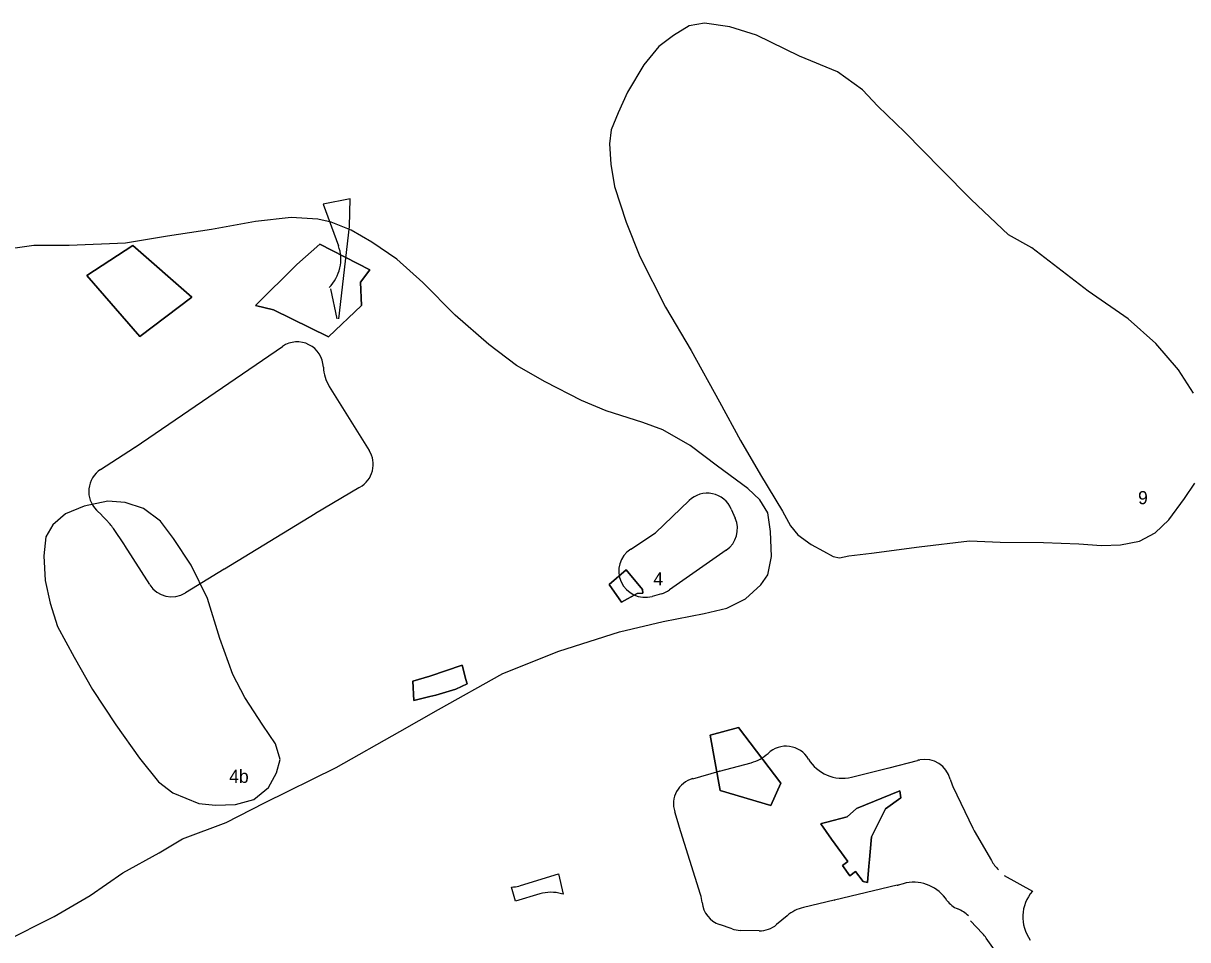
# Model space of a CAD drawing. Extents: x -445049 to -430649, y -1142304 to -1129816.
# Drawn here: x -443912 to -443023, y -1133134 to -1132434 of the extents above; entities that cross this region are included whole.
import ezdxf

# ---------------------------------------------------------------- set-up
doc = ezdxf.new("R2010")
doc.units = 0
for name, color, linetype in [('Vrstva 23', 7, 'Continuous'), ('Vrstva 51', 7, 'Continuous'), ('Vrstva 7', 7, 'Continuous')]:
    doc.layers.add(name, color=color, linetype=linetype)

msp = doc.modelspace()

# ---------------------------------------------------------------- linework, layer by layer
at = {"layer": 'Vrstva 23'}
for p, q in [((-443677.2, -1132636.66), (-443672.36, -1132659.53)), ((-443826.33, -1132757.45), (-443713.91, -1132680.67)), ((-443678.1, -1132711.26), (-443647.59, -1132760.03)), ((-443852.69, -1132774.68), (-443826.84, -1132757.8)), ((-443655.53, -1132788.52), (-443688.59, -1132808.22)), ((-443851.84, -1132809.61), (-443855.88, -1132805.59)), ((-443688.86, -1132808.38), (-443758.18, -1132850.65)), ((-443371.2, -1132804.79), (-443368.17, -1132811.8)), ((-443845.46, -1132816.41), (-443848.81, -1132812.68)), ((-443834.59, -1132832.03), (-443842.94, -1132819.65)), ((-443815.22, -1132862.54), (-443834.13, -1132832.74)), ((-443375.02, -1132836.12), (-443418.43, -1132866.6)), ((-443758.26, -1132850.7), (-443787.87, -1132868.88)), ((-443424.57, -1132869.5), (-443431.72, -1132871.48)), ((-443250.62, -1133002.33), (-443229.15, -1132996.77)), ((-443228.1, -1132996.53), (-443227.4, -1132996.39)), ((-443400.71, -1133010.65), (-443380.4, -1133005.02)), ((-443380.26, -1133004.98), (-443355.96, -1132998.44)), ((-443279.39, -1133009.4), (-443250.99, -1133002.43)), ((-443202.04, -1133016.63), (-443186.84, -1133048.43)), ((-443410.96, -1133046.98), (-443414.44, -1133035.94)), ((-443394.67, -1133099.04), (-443410.94, -1133047.05)), ((-443185.78, -1133050.44), (-443172.68, -1133073.24)), ((-443162.86, -1133084.64), (-443141.31, -1133096.58)), ((-443244.47, -1133092.05), (-443292.56, -1133103.48)), ((-443239.99, -1133090.82), (-443243.74, -1133091.86)), ((-443499.6, -1133098.8), (-443500.76, -1133098.48)), ((-443292.65, -1133103.51), (-443316.12, -1133108.96)), ((-443206.59, -1133103.57), (-443207.78, -1133101.95)), ((-443370.67, -1133125.37), (-443380.11, -1133122.07)), ((-443332.71, -1133118.66), (-443336.64, -1133122.01)), ((-443328.69, -1133115.27), (-443332.62, -1133118.58)), ((-443179.41, -1133128.87), (-443188.71, -1133119.22)), ((-443350.04, -1133126.78), (-443364.51, -1133126.48))]:
    msp.add_line(p, q, dxfattribs=at)
for points in [[(-443670.87, -1132659.7), (-443662.77, -1132589.04), (-443662.25, -1132567.97), (-443682.82, -1132572.18), (-443671.15, -1132603.81)], [(-443448.03, -1132835.48), (-443428.97, -1132822.99), (-443403.44, -1132798.36)], [(-443532.2, -1133092.22), (-443503.17, -1133083.21), (-443499.6, -1133098.8)], [(-443517.4, -1133098.66), (-443535.96, -1133104.24), (-443538.96, -1133093.54), (-443537.4, -1133093.34)], [(-443103.8, -1133213.9), (-443113.59, -1133220.86), (-443176.56, -1133132.31)]]:
    msp.add_lwpolyline(points, dxfattribs=at)
for centre, radius, start, end in [((-443699.29, -1132614.2), 30, 314.42043, 20.25618), ((-443702.63, -1132697.18), 20, 2.10176, 124.3337), ((-443652.66, -1132695.35), 30, 182.10176, 212.02791), ((-443843.25, -1132732.68), 30, 303.15924, 304.33371), ((-443664.54, -1132770.64), 20, 299.16865, 32.02791), ((-443841.75, -1132791.43), 20, 123.15924, 225.0635), ((-443640.18, -1132814.3), 30, 119.16865, 120.78723), ((-443389.55, -1132812.75), 20, 23.43675, 133.9791), ((-443873.03, -1132830.85), 30, 44.03693, 45.0635), ((-443837.09, -1132796.1), 20, 224.03693, 227.0475), ((-443871.16, -1132832.69), 30, 41.84119, 47.0475), ((-443673.24, -1132834), 30, 120.78723, 121.37077), ((-443867.81, -1132836.43), 30, 33.99357, 41.84119), ((-443386.51, -1132819.75), 20, 305.071, 23.43675), ((-443859.46, -1132848.8), 30, 32.38493, 33.99357), ((-443437.07, -1132852.21), 20, 123.2296, 285.51431), ((-443742.57, -1132876.27), 30, 121.37077, 121.54625), ((-443798.34, -1132851.83), 20, 212.38493, 301.54625), ((-443429.92, -1132850.23), 20, 285.51431, 305.071), ((-443329.49, -1133005.88), 20, 30.81364, 133.26556), ((-443363.76, -1132969.47), 30, 285.07078, 313.26556), ((-443286.55, -1132980.27), 30, 210.81364, 283.80053), ((-443224.13, -1133016.13), 20, 101.44355, 104.52763), ((-443223.43, -1133015.99), 20, 14.23712, 101.44355), ((-443375.06, -1133024.3), 20, 105.07078, 105.47705), ((-443258.15, -1132973.29), 30, 283.80053, 284.52763), ((-443395.37, -1133029.92), 20, 105.47705, 197.51206), ((-443174.97, -1133003.69), 30, 194.23712, 205.54552), ((-443439.57, -1133056.01), 30, 17.38, 17.51206), ((-443159.77, -1133035.49), 30, 205.54552, 209.88212), ((-443146.67, -1133058.29), 30, 209.88212, 226.72454), ((-443541.09, -1133063.57), 30, 277.06067, 287.23966), ((-443249.1, -1133072.59), 20, 283.37402, 285.53896), ((-443231.95, -1133119.72), 30, 36.33833, 105.53896), ((-443508.76, -1133127.39), 30, 74.53249, 106.73425), ((-443423.3, -1133108), 30, 5.52393, 17.38), ((-443297.18, -1133084.03), 20, 283.08603, 283.37402), ((-443190.48, -1133091.72), 20, 216.33833, 246.75567), ((-443118.68, -1133116.27), 30, 138.97955, 215.86626), ((-443373.53, -1133103.19), 20, 185.52393, 250.77659), ((-443309.33, -1133138.18), 30, 103.08603, 130.19033), ((-443210.21, -1133137.66), 30, 48.01849, 66.75567), ((-443349.61, -1133106.79), 20, 268.784, 310.4326), ((-443313.26, -1133141.5), 30, 130.19033, 130.4326), ((-443364.08, -1133106.48), 20, 250.77659, 268.784), ((-443201.01, -1133149.69), 30, 35.41387, 43.94189)]:
    msp.add_arc(centre, radius, start, end, dxfattribs=at)
at = {"layer": 'Vrstva 51'}
for points in [[(-443018.34, -1132716.27), (-443029.71, -1132698.63), (-443047.02, -1132678.5), (-443068.13, -1132659.72), (-443098.88, -1132638.57), (-443125.18, -1132618.17), (-443141.83, -1132605.46), (-443159.51, -1132595.53), (-443188.17, -1132568.41), (-443211, -1132545.4), (-443238.76, -1132517.11), (-443259.36, -1132497.14), (-443271.13, -1132484.8), (-443290.15, -1132471.08), (-443319.14, -1132459.08), (-443351.91, -1132443.11), (-443372.31, -1132436.66), (-443391.75, -1132433.97), (-443403.37, -1132435.96), (-443415.38, -1132443.25), (-443426.66, -1132451.81), (-443437.94, -1132465.7), (-443450.56, -1132486.45), (-443457.48, -1132502.31), (-443462.97, -1132515.4), (-443464.17, -1132525.96), (-443463.3, -1132541.58), (-443460.48, -1132558.57), (-443451.48, -1132585.86), (-443441.17, -1132612.02), (-443421.56, -1132650.74), (-443401.94, -1132683.74), (-443380.33, -1132723.03), (-443364.12, -1132752.49), (-443348.89, -1132778.61), (-443332.16, -1132806.48), (-443326.03, -1132817.58), (-443320.42, -1132824.56), (-443310.32, -1132831.86), (-443300.89, -1132837.08), (-443293.4, -1132840.92), (-443288.58, -1132842.1), (-443281.5, -1132840.58), (-443264.16, -1132838.61), (-443227.76, -1132833.57), (-443189.35, -1132829.09), (-443166.08, -1132830.02), (-443132.96, -1132830.46), (-443106, -1132831.26), (-443088.5, -1132832.58), (-443074.13, -1132832.02), (-443059.6, -1132829.43), (-443047.65, -1132822.96), (-443037.09, -1132813.11), (-443025.22, -1132796.81), (-443017.38, -1132785.12)], [(-443926.51, -1133135.09), (-443888.12, -1133115.97), (-443860.74, -1133099.76), (-443835.78, -1133082.54), (-443808.05, -1133067.18), (-443790.22, -1133056.48), (-443756.9, -1133044.04), (-443727.55, -1133029.22), (-443672.79, -1133002.2), (-443624.21, -1132974.71), (-443594.71, -1132957.83), (-443545.73, -1132930.37), (-443502.92, -1132913.24), (-443456.55, -1132898.46), (-443423.15, -1132890.59), (-443391.98, -1132884.63), (-443374.65, -1132880.53), (-443360.4, -1132873.3), (-443348.79, -1132862.55), (-443343.25, -1132855.08), (-443340.54, -1132841.16), (-443341.18, -1132822.01), (-443343.43, -1132807.73), (-443349.32, -1132797.73), (-443358.64, -1132789.14), (-443381.85, -1132772.04), (-443402.68, -1132756.35), (-443423.37, -1132744.42), (-443438.72, -1132738.69), (-443466.71, -1132729.95), (-443485.62, -1132721.88), (-443513.21, -1132707.76), (-443535.11, -1132695.32), (-443556.32, -1132679.2), (-443582.05, -1132656.92), (-443606.74, -1132631.81), (-443626.58, -1132614.12), (-443645.53, -1132601.07), (-443661.46, -1132591.98), (-443676.77, -1132585.85), (-443686.97, -1132583.42), (-443707.23, -1132582.31), (-443734.44, -1132585.25), (-443768.13, -1132591.44), (-443801.72, -1132596.39), (-443833.69, -1132601.87), (-443876.58, -1132603.63), (-443903.58, -1132603.67), (-443930.85, -1132607.44)]]:
    msp.add_lwpolyline(points, dxfattribs=at)
msp.add_lwpolyline([(-443894.56, -1132826.08), (-443896.06, -1132840.5), (-443894.98, -1132859.26), (-443891.29, -1132876.57), (-443885.58, -1132894.43), (-443872.8, -1132917.82), (-443858.88, -1132942.53), (-443840.99, -1132969.62), (-443822.97, -1132995.06), (-443808.56, -1133013.16), (-443797.55, -1133021.47), (-443777.82, -1133029.59), (-443765.05, -1133030.97), (-443749.65, -1133030.47), (-443735.65, -1133026.54), (-443724.59, -1133017.4), (-443718.35, -1133006.25), (-443715.51, -1132996.08), (-443719.18, -1132984.18), (-443728.89, -1132969.74), (-443742.68, -1132948.78), (-443751.73, -1132931.07), (-443761.71, -1132903.75), (-443771.04, -1132873.15), (-443783.66, -1132847.7), (-443797.06, -1132827.18), (-443806.87, -1132813.99), (-443819.84, -1132804.29), (-443834.04, -1132799.9), (-443847.25, -1132798.91), (-443865.38, -1132802.53), (-443879.53, -1132808.52), (-443889.3, -1132816.92)], close=True, dxfattribs=at)
at = {"layer": 'Vrstva 7'}
for points in [[(-443828.15, -1132603.55), (-443863.1, -1132626.63), (-443822.73, -1132673.2), (-443783.07, -1132643.01)], [(-443647.09, -1132622.27), (-443685.3, -1132602.68), (-443702.95, -1132618), (-443734.43, -1132649.42), (-443720.76, -1132652.69), (-443678.64, -1132673.29), (-443653.44, -1132649.34), (-443654.17, -1132631.61)], [(-443451.46, -1132851.14), (-443464.57, -1132862.35), (-443456.8, -1132873.4), (-443455.08, -1132875.85), (-443443.13, -1132869.24), (-443438.81, -1132868.96), (-443439.05, -1132866.23)], [(-443614.24, -1132936.31), (-443613.52, -1132951.03), (-443601.24, -1132948), (-443596.87, -1132946.92), (-443581.63, -1132942.44), (-443572.9, -1132938.2), (-443573.78, -1132934.82), (-443576.57, -1132924.01), (-443601.31, -1132932.37)], [(-443365.67, -1132971.65), (-443387.46, -1132977.55), (-443379.8, -1133019.76), (-443341.01, -1133031.01), (-443333.3, -1133014.03)], [(-443242.5, -1133019.89), (-443275.64, -1133033.38), (-443282.8, -1133039.75), (-443298.4, -1133043.79), (-443302.31, -1133044.8), (-443302.95, -1133045.12), (-443294.61, -1133056.94), (-443282.3, -1133073.98), (-443286.39, -1133076.88), (-443280.78, -1133084.79), (-443276.33, -1133081.63), (-443270.55, -1133089.05), (-443267.19, -1133089.91), (-443266.16, -1133077.45), (-443265.74, -1133072.42), (-443265.24, -1133066.45), (-443264.3, -1133055.13), (-443262.99, -1133052.52), (-443253.53, -1133033.63), (-443241.79, -1133025.28)]]:
    msp.add_lwpolyline(points, close=True, dxfattribs=at)
for points in [[(-443828.15, -1132603.55), (-443783.07, -1132643.01), (-443822.73, -1132673.2), (-443863.1, -1132626.63), (-443828.15, -1132603.55)], [(-443863.1, -1132626.63), (-443828.15, -1132603.55), (-443783.07, -1132643.01), (-443822.73, -1132673.2), (-443863.1, -1132626.63)], [(-443828.15, -1132603.55), (-443783.07, -1132643.01), (-443822.73, -1132673.2), (-443863.1, -1132626.63), (-443828.15, -1132603.55)], [(-443822.73, -1132673.2), (-443863.1, -1132626.63), (-443828.15, -1132603.55), (-443783.07, -1132643.01), (-443822.73, -1132673.2)], [(-443647.09, -1132622.27), (-443654.17, -1132631.61), (-443653.44, -1132649.34), (-443678.64, -1132673.29), (-443720.76, -1132652.69), (-443734.43, -1132649.42), (-443702.95, -1132618), (-443685.3, -1132602.68), (-443647.09, -1132622.27)], [(-443685.3, -1132602.68), (-443647.09, -1132622.27), (-443654.17, -1132631.61), (-443653.44, -1132649.34), (-443678.64, -1132673.29), (-443720.76, -1132652.69), (-443734.43, -1132649.42), (-443702.95, -1132618), (-443685.3, -1132602.68)], [(-443734.43, -1132649.42), (-443702.95, -1132618), (-443685.3, -1132602.68), (-443647.09, -1132622.27), (-443654.17, -1132631.61), (-443653.44, -1132649.34), (-443678.64, -1132673.29), (-443720.76, -1132652.69), (-443734.43, -1132649.42)], [(-443720.76, -1132652.69), (-443734.43, -1132649.42), (-443702.95, -1132618), (-443685.3, -1132602.68), (-443647.09, -1132622.27), (-443654.17, -1132631.61), (-443653.44, -1132649.34), (-443678.64, -1132673.29), (-443720.76, -1132652.69)], [(-443451.46, -1132851.14), (-443439.05, -1132866.23), (-443438.81, -1132868.96), (-443443.13, -1132869.24), (-443455.08, -1132875.85), (-443456.8, -1132873.4), (-443464.57, -1132862.35), (-443451.46, -1132851.14)], [(-443456.8, -1132873.4), (-443464.57, -1132862.35), (-443451.46, -1132851.14), (-443439.05, -1132866.23), (-443438.81, -1132868.96), (-443443.13, -1132869.24), (-443455.08, -1132875.85), (-443456.8, -1132873.4)], [(-443443.13, -1132869.24), (-443455.08, -1132875.85), (-443456.8, -1132873.4), (-443464.57, -1132862.35), (-443451.46, -1132851.14), (-443439.05, -1132866.23), (-443438.81, -1132868.96), (-443443.13, -1132869.24)], [(-443443.13, -1132869.24), (-443455.08, -1132875.85), (-443456.8, -1132873.4), (-443464.57, -1132862.35), (-443451.46, -1132851.14), (-443439.05, -1132866.23), (-443438.81, -1132868.96), (-443443.13, -1132869.24)], [(-443614.24, -1132936.31), (-443601.31, -1132932.37), (-443576.57, -1132924.01), (-443573.78, -1132934.82), (-443572.9, -1132938.2), (-443581.63, -1132942.44), (-443596.87, -1132946.92), (-443601.24, -1132948), (-443613.52, -1132951.03), (-443614.24, -1132936.31)], [(-443601.24, -1132948), (-443613.52, -1132951.03), (-443614.24, -1132936.31), (-443601.31, -1132932.37), (-443576.57, -1132924.01), (-443573.78, -1132934.82), (-443572.9, -1132938.2), (-443581.63, -1132942.44), (-443596.87, -1132946.92), (-443601.24, -1132948)], [(-443596.87, -1132946.92), (-443601.24, -1132948), (-443613.52, -1132951.03), (-443614.24, -1132936.31), (-443601.31, -1132932.37), (-443576.57, -1132924.01), (-443573.78, -1132934.82), (-443572.9, -1132938.2), (-443581.63, -1132942.44), (-443596.87, -1132946.92)], [(-443365.67, -1132971.65), (-443333.3, -1133014.03), (-443341.01, -1133031.01), (-443379.8, -1133019.76), (-443387.46, -1132977.55), (-443365.67, -1132971.65)], [(-443387.46, -1132977.55), (-443365.67, -1132971.65), (-443333.3, -1133014.03), (-443341.01, -1133031.01), (-443379.8, -1133019.76), (-443387.46, -1132977.55)], [(-443333.3, -1133014.03), (-443341.01, -1133031.01), (-443379.8, -1133019.76), (-443387.46, -1132977.55), (-443365.67, -1132971.65), (-443333.3, -1133014.03)], [(-443341.01, -1133031.01), (-443379.8, -1133019.76), (-443387.46, -1132977.55), (-443365.67, -1132971.65), (-443333.3, -1133014.03), (-443341.01, -1133031.01)], [(-443242.5, -1133019.89), (-443241.79, -1133025.28), (-443253.53, -1133033.63), (-443262.99, -1133052.52), (-443264.3, -1133055.13), (-443265.24, -1133066.45), (-443265.74, -1133072.42), (-443266.16, -1133077.45), (-443267.19, -1133089.91), (-443270.55, -1133089.05), (-443276.33, -1133081.63), (-443280.78, -1133084.79), (-443286.39, -1133076.88), (-443282.3, -1133073.98), (-443294.61, -1133056.94), (-443302.95, -1133045.12), (-443302.31, -1133044.8), (-443298.4, -1133043.79), (-443282.8, -1133039.75), (-443275.64, -1133033.38), (-443242.5, -1133019.89)], [(-443275.64, -1133033.38), (-443242.5, -1133019.89), (-443241.79, -1133025.28), (-443253.53, -1133033.63), (-443262.99, -1133052.52), (-443264.3, -1133055.13), (-443265.24, -1133066.45), (-443265.74, -1133072.42), (-443266.16, -1133077.45), (-443267.19, -1133089.91), (-443270.55, -1133089.05), (-443276.33, -1133081.63), (-443280.78, -1133084.79), (-443286.39, -1133076.88), (-443282.3, -1133073.98), (-443294.61, -1133056.94), (-443302.95, -1133045.12), (-443302.31, -1133044.8), (-443298.4, -1133043.79), (-443282.8, -1133039.75), (-443275.64, -1133033.38)], [(-443298.4, -1133043.79), (-443282.8, -1133039.75), (-443275.64, -1133033.38), (-443242.5, -1133019.89), (-443241.79, -1133025.28), (-443253.53, -1133033.63), (-443262.99, -1133052.52), (-443264.3, -1133055.13), (-443265.24, -1133066.45), (-443265.74, -1133072.42), (-443266.16, -1133077.45), (-443267.19, -1133089.91), (-443270.55, -1133089.05), (-443276.33, -1133081.63), (-443280.78, -1133084.79), (-443286.39, -1133076.88), (-443282.3, -1133073.98), (-443294.61, -1133056.94), (-443302.95, -1133045.12), (-443302.31, -1133044.8), (-443298.4, -1133043.79)], [(-443280.78, -1133084.79), (-443286.39, -1133076.88), (-443282.3, -1133073.98), (-443294.61, -1133056.94), (-443302.95, -1133045.12), (-443302.31, -1133044.8), (-443298.4, -1133043.79), (-443282.8, -1133039.75), (-443275.64, -1133033.38), (-443242.5, -1133019.89), (-443241.79, -1133025.28), (-443253.53, -1133033.63), (-443262.99, -1133052.52), (-443264.3, -1133055.13), (-443265.24, -1133066.45), (-443265.74, -1133072.42), (-443266.16, -1133077.45), (-443267.19, -1133089.91), (-443270.55, -1133089.05), (-443276.33, -1133081.63), (-443280.78, -1133084.79)]]:
    msp.add_lwpolyline(points, dxfattribs=at)

# ---------------------------------------------------------------- texts
at = {"layer": 'Vrstva 51'}
for s, p in [('9', (-443060.7, -1132801.11)), ('4', (-443430.69, -1132863.04)), ('4b', (-443754.53, -1133013.85))]:
    msp.add_text(s, height=10, dxfattribs=at).set_placement(p)

doc.saveas('drawing.dxf')
